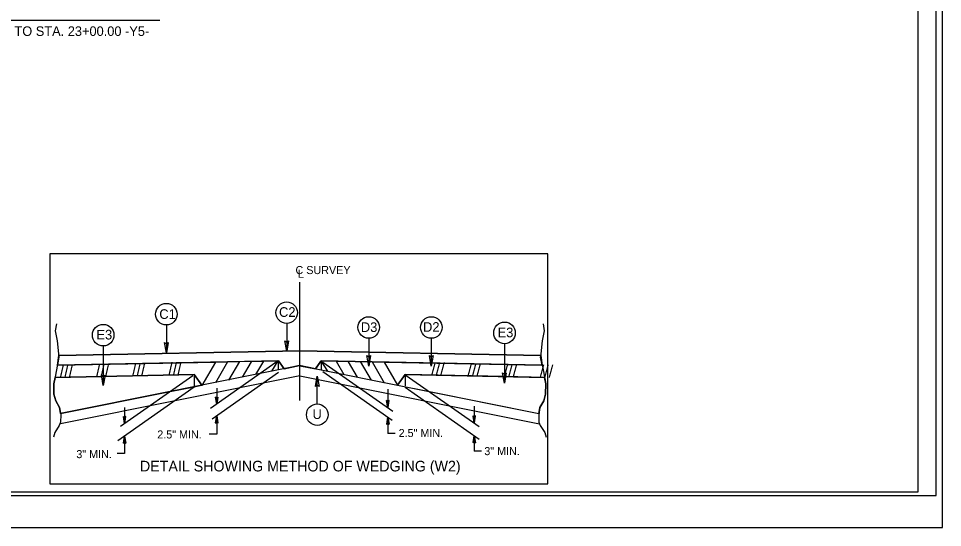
# Model space of a CAD drawing. Extents: x 2176156 to 2177167, y 76401 to 76644.
# Drawn here: x 2176795 to 2176898.7, y 76454.5 to 76511.6 of the extents above; entities that cross this region are included whole.
import ezdxf

# ---------------------------------------------------------------- set-up
doc = ezdxf.new("R2010")
doc.units = 0
for name, color, linetype in [('Exist Other Culture Fence Line', 7, 'Continuous'), ('Exist Utilities Water Fire Hydrant CELL', 7, 'Continuous'), ('Exist Vegetation Hedge Row', 7, 'Continuous'), ('Exist Vegetation Shrub CELL', 7, 'Continuous'), ('Exist Vegetation Woods Line', 7, 'Continuous'), ('Model Boundary Lines', 7, 'Continuous'), ('Model Boundary Lines Text', 7, 'Continuous'), ('Old_Level_1', 7, 'Continuous'), ('Prop North Arrow NAD83 for Plan Sheets CELL', 7, 'Continuous'), ('Scratch_Level_0', 7, 'Continuous'), ('Sheet Cutting Line CELL', 7, 'Continuous'), ('Sheet Data Field CELL', 7, 'Continuous'), ('Sheet Plot Border Outside CELL', 7, 'Continuous'), ('Sheet Sticker Exception Certification CELL', 7, 'Continuous')]:
    doc.layers.add(name, color=color, linetype=linetype)

msp = doc.modelspace()

# ---------------------------------------------------------------- linework, layer by layer
at = {"layer": 'Exist Other Culture Fence Line'}
msp.add_lwpolyline([(2176798.48, 76459.39), (2176854.4, 76459.39), (2176854.4, 76485.21), (2176798.48, 76485.21)], close=True, dxfattribs=at)
at = {"layer": 'Exist Utilities Water Fire Hydrant CELL'}
for p, q in [((2176799.33, 76472.69), (2176799.48, 76473.78)), ((2176826.54, 76474.32), (2176799.48, 76473.78)), ((2176799.48, 76473.78), (2176826.54, 76474.32)), ((2176826.54, 76474.32), (2176853.6, 76473.78)), ((2176826.54, 76474.32), (2176853.6, 76473.78)), ((2176853.6, 76473.78), (2176853.75, 76472.69)), ((2176824.17, 76473.19), (2176799.33, 76472.69)), ((2176824.17, 76473.19), (2176799.33, 76472.69)), ((2176826.58, 76472.65), (2176799.69, 76467.27)), ((2176817.07, 76473.04), (2176815.53, 76470.41)), ((2176824.13, 76473.17), (2176816.51, 76467.83)), ((2176818.42, 76473.07), (2176817.06, 76470.73)), ((2176819.76, 76473.1), (2176818.53, 76471)), ((2176821.1, 76473.09), (2176820.09, 76471.36)), ((2176822.46, 76473.16), (2176821.58, 76471.65)), ((2176823.4, 76472.03), (2176824.13, 76473.18)), ((2176824.13, 76473.18), (2176824.13, 76472.23)), ((2176824.77, 76472.29), (2176824.17, 76473.19)), ((2176824.17, 76473.16), (2176824.77, 76472.29)), ((2176826.5, 76472.65), (2176824.77, 76472.29)), ((2176826.5, 76472.65), (2176853.39, 76467.27)), ((2176828.3, 76472.29), (2176826.5, 76472.65)), ((2176828.93, 76473.19), (2176828.3, 76472.29)), ((2176828.93, 76473.19), (2176828.3, 76472.29)), ((2176828.89, 76473.17), (2176828.93, 76473.16)), ((2176828.93, 76473.19), (2176853.75, 76472.69)), ((2176853.75, 76472.69), (2176828.93, 76473.19)), ((2176829.68, 76472.03), (2176828.95, 76473.18)), ((2176828.95, 76473.18), (2176828.95, 76472.14)), ((2176829.14, 76473.04), (2176836.99, 76467.54)), ((2176830.62, 76473.16), (2176831.5, 76471.65)), ((2176831.98, 76473.09), (2176832.99, 76471.36)), ((2176833.32, 76473.1), (2176834.54, 76471)), ((2176834.66, 76473.07), (2176836.02, 76470.73)), ((2176836.01, 76473.04), (2176837.52, 76470.45)), ((2176814.7, 76471.64), (2176799.07, 76471.33)), ((2176799.07, 76471.33), (2176814.7, 76471.64)), ((2176814.52, 76471.51), (2176806.4, 76465.82)), ((2176815.55, 76470.44), (2176814.7, 76471.64)), ((2176814.7, 76471.64), (2176814.7, 76470.38)), ((2176814.7, 76471.64), (2176815.55, 76470.45)), ((2176824.15, 76471.86), (2176816.69, 76466.64)), ((2176829.13, 76471.97), (2176836.91, 76466.53)), ((2176838.37, 76471.64), (2176837.52, 76470.45)), ((2176837.53, 76470.45), (2176838.37, 76471.64)), ((2176838.37, 76471.64), (2176854.01, 76471.33)), ((2176838.37, 76471.64), (2176838.37, 76470.37)), ((2176849.53, 76471.42), (2176838.37, 76471.64)), ((2176838.5, 76471.55), (2176846.69, 76465.82)), ((2176826.53, 76471.5), (2176799.68, 76466.12)), ((2176826.55, 76471.5), (2176853.46, 76466.11)), ((2176854.01, 76471.33), (2176849.53, 76471.42)), ((2176811.98, 76469.73), (2176799.69, 76467.27)), ((2176814.7, 76470.23), (2176806.11, 76464.19)), ((2176814.7, 76470.28), (2176811.98, 76469.73)), ((2176815.55, 76470.45), (2176814.7, 76470.28)), ((2176817.21, 76470.13), (2176817.21, 76468.31)), ((2176836.42, 76470.02), (2176836.42, 76467.94)), ((2176837.52, 76470.45), (2176841.1, 76469.73)), ((2176838.37, 76470.21), (2176846.68, 76464.39)), ((2176841.1, 76469.73), (2176853.39, 76467.27)), ((2176817.21, 76468.31), (2176817.07, 76469.11)), ((2176817.21, 76469), (2176817.07, 76469.11)), ((2176817.21, 76468.31), (2176817.09, 76469.09)), ((2176817.11, 76469.08), (2176817.21, 76468.31)), ((2176817.21, 76468.31), (2176817.13, 76469.06)), ((2176817.15, 76469.05), (2176817.21, 76468.31)), ((2176817.21, 76468.31), (2176817.17, 76469.03)), ((2176817.19, 76469.02), (2176817.21, 76468.31)), ((2176817.21, 76468.31), (2176817.35, 76469.11)), ((2176817.35, 76469.11), (2176817.21, 76469)), ((2176817.33, 76469.09), (2176817.21, 76468.31)), ((2176817.21, 76468.31), (2176817.31, 76469.08)), ((2176817.29, 76469.06), (2176817.21, 76468.31)), ((2176817.21, 76468.31), (2176817.27, 76469.05)), ((2176817.25, 76469.03), (2176817.21, 76468.31)), ((2176817.21, 76468.31), (2176817.23, 76469.02)), ((2176817.21, 76469), (2176817.21, 76468.31)), ((2176836.42, 76467.94), (2176836.28, 76468.74)), ((2176836.42, 76468.64), (2176836.28, 76468.74)), ((2176836.42, 76467.94), (2176836.3, 76468.72)), ((2176836.32, 76468.71), (2176836.42, 76467.94)), ((2176836.42, 76467.94), (2176836.34, 76468.69)), ((2176836.36, 76468.68), (2176836.42, 76467.94)), ((2176836.42, 76467.94), (2176836.38, 76468.67)), ((2176836.4, 76468.65), (2176836.42, 76467.94)), ((2176836.42, 76467.94), (2176836.56, 76468.74)), ((2176836.56, 76468.74), (2176836.42, 76468.64)), ((2176836.54, 76468.72), (2176836.42, 76467.94)), ((2176836.42, 76467.94), (2176836.52, 76468.71)), ((2176836.5, 76468.69), (2176836.42, 76467.94)), ((2176836.42, 76467.94), (2176836.48, 76468.68)), ((2176836.46, 76468.67), (2176836.42, 76467.94)), ((2176836.42, 76467.94), (2176836.44, 76468.65)), ((2176836.42, 76468.64), (2176836.42, 76467.94)), ((2176806.87, 76467.96), (2176806.87, 76466.15)), ((2176846.13, 76468.09), (2176846.13, 76466.21)), ((2176806.87, 76466.15), (2176806.73, 76466.95)), ((2176806.87, 76466.84), (2176806.73, 76466.95)), ((2176806.87, 76466.15), (2176806.75, 76466.93)), ((2176806.77, 76466.92), (2176806.87, 76466.15)), ((2176806.87, 76466.15), (2176806.79, 76466.9)), ((2176806.81, 76466.89), (2176806.87, 76466.15)), ((2176806.87, 76466.15), (2176806.83, 76466.87)), ((2176806.85, 76466.86), (2176806.87, 76466.15)), ((2176806.87, 76466.15), (2176807.01, 76466.95)), ((2176807.01, 76466.95), (2176806.87, 76466.84)), ((2176806.99, 76466.93), (2176806.87, 76466.15)), ((2176806.87, 76466.15), (2176806.97, 76466.92)), ((2176806.95, 76466.9), (2176806.87, 76466.15)), ((2176806.87, 76466.15), (2176806.93, 76466.89)), ((2176806.91, 76466.87), (2176806.87, 76466.15)), ((2176806.87, 76466.15), (2176806.89, 76466.86)), ((2176806.87, 76466.84), (2176806.87, 76466.15)), ((2176817.21, 76467), (2176817.07, 76466.2)), ((2176817.09, 76466.22), (2176817.21, 76467)), ((2176817.21, 76467), (2176817.11, 76466.23)), ((2176817.13, 76466.25), (2176817.21, 76467)), ((2176817.21, 76467), (2176817.15, 76466.26)), ((2176817.17, 76466.27), (2176817.21, 76467)), ((2176817.21, 76467), (2176817.19, 76466.29)), ((2176817.21, 76467), (2176817.21, 76464.95)), ((2176817.21, 76467), (2176817.35, 76466.2)), ((2176817.21, 76466.3), (2176817.21, 76467)), ((2176817.23, 76466.29), (2176817.21, 76467)), ((2176817.21, 76467), (2176817.25, 76466.27)), ((2176817.27, 76466.26), (2176817.21, 76467)), ((2176817.21, 76467), (2176817.29, 76466.25)), ((2176817.31, 76466.23), (2176817.21, 76467)), ((2176817.21, 76467), (2176817.33, 76466.22)), ((2176836.42, 76466.87), (2176836.28, 76466.07)), ((2176836.3, 76466.09), (2176836.42, 76466.87)), ((2176836.42, 76466.87), (2176836.32, 76466.1)), ((2176836.34, 76466.12), (2176836.42, 76466.87)), ((2176836.42, 76466.87), (2176836.36, 76466.13)), ((2176836.38, 76466.15), (2176836.42, 76466.87)), ((2176836.42, 76466.87), (2176836.4, 76466.16)), ((2176836.42, 76466.87), (2176836.42, 76465.01)), ((2176836.42, 76466.87), (2176836.56, 76466.07)), ((2176836.42, 76466.17), (2176836.42, 76466.87)), ((2176836.44, 76466.16), (2176836.42, 76466.87)), ((2176836.42, 76466.87), (2176836.46, 76466.15)), ((2176836.48, 76466.13), (2176836.42, 76466.87)), ((2176836.42, 76466.87), (2176836.5, 76466.12)), ((2176836.52, 76466.1), (2176836.42, 76466.87)), ((2176836.42, 76466.87), (2176836.54, 76466.09)), ((2176846.13, 76466.21), (2176845.99, 76467.01)), ((2176846.13, 76466.9), (2176845.99, 76467.01)), ((2176846.13, 76466.21), (2176846.01, 76466.99)), ((2176846.03, 76466.98), (2176846.13, 76466.21)), ((2176846.13, 76466.21), (2176846.05, 76466.96)), ((2176846.07, 76466.95), (2176846.13, 76466.21)), ((2176846.13, 76466.21), (2176846.09, 76466.93)), ((2176846.11, 76466.92), (2176846.13, 76466.21)), ((2176846.13, 76466.21), (2176846.27, 76467.01)), ((2176846.27, 76467.01), (2176846.13, 76466.9)), ((2176846.25, 76466.99), (2176846.13, 76466.21)), ((2176846.13, 76466.21), (2176846.23, 76466.98)), ((2176846.21, 76466.96), (2176846.13, 76466.21)), ((2176846.13, 76466.21), (2176846.19, 76466.95)), ((2176846.17, 76466.93), (2176846.13, 76466.21)), ((2176846.13, 76466.21), (2176846.15, 76466.92)), ((2176846.13, 76466.9), (2176846.13, 76466.21)), ((2176817.07, 76466.2), (2176817.21, 76466.3)), ((2176817.21, 76466.3), (2176817.35, 76466.2)), ((2176836.28, 76466.07), (2176836.42, 76466.17)), ((2176836.42, 76466.17), (2176836.56, 76466.07)), ((2176806.87, 76464.72), (2176806.73, 76463.93)), ((2176806.75, 76463.94), (2176806.87, 76464.72)), ((2176806.87, 76464.72), (2176806.77, 76463.95)), ((2176806.79, 76463.97), (2176806.87, 76464.72)), ((2176806.87, 76464.72), (2176806.81, 76463.98)), ((2176806.83, 76464), (2176806.87, 76464.72)), ((2176806.87, 76464.72), (2176806.85, 76464.01)), ((2176806.87, 76464.72), (2176806.87, 76462.79)), ((2176806.87, 76464.72), (2176807.01, 76463.93)), ((2176806.87, 76464.03), (2176806.87, 76464.72)), ((2176806.89, 76464.01), (2176806.87, 76464.72)), ((2176806.87, 76464.72), (2176806.91, 76464)), ((2176806.93, 76463.98), (2176806.87, 76464.72)), ((2176806.87, 76464.72), (2176806.95, 76463.97)), ((2176806.97, 76463.95), (2176806.87, 76464.72)), ((2176806.87, 76464.72), (2176806.99, 76463.94)), ((2176817.21, 76464.95), (2176816.37, 76464.95)), ((2176837.25, 76465.01), (2176836.42, 76465.01)), ((2176846.13, 76464.78), (2176845.99, 76463.98)), ((2176846.01, 76464), (2176846.13, 76464.78)), ((2176846.13, 76464.78), (2176846.03, 76464.01)), ((2176846.05, 76464.03), (2176846.13, 76464.78)), ((2176846.13, 76464.78), (2176846.07, 76464.04)), ((2176846.09, 76464.06), (2176846.13, 76464.78)), ((2176846.13, 76464.78), (2176846.11, 76464.07)), ((2176846.13, 76464.78), (2176846.13, 76463.03)), ((2176846.13, 76464.78), (2176846.27, 76463.98)), ((2176846.13, 76464.09), (2176846.13, 76464.78)), ((2176846.15, 76464.07), (2176846.13, 76464.78)), ((2176846.13, 76464.78), (2176846.17, 76464.06)), ((2176846.19, 76464.04), (2176846.13, 76464.78)), ((2176846.13, 76464.78), (2176846.21, 76464.03)), ((2176846.23, 76464.01), (2176846.13, 76464.78)), ((2176846.13, 76464.78), (2176846.25, 76464)), ((2176806.73, 76463.93), (2176806.87, 76464.03)), ((2176806.87, 76464.03), (2176807.01, 76463.93)), ((2176845.99, 76463.98), (2176846.13, 76464.09)), ((2176846.13, 76464.09), (2176846.27, 76463.98)), ((2176806.87, 76462.79), (2176806.03, 76462.79)), ((2176846.96, 76463.03), (2176846.13, 76463.03))]:
    msp.add_line(p, q, dxfattribs=at)
for points in [[(2176799.23, 76477.35), (2176799.09, 76476.55), (2176799.3, 76475.43), (2176799.5, 76473.6), (2176799.23, 76472.16), (2176798.92, 76470.6), (2176798.94, 76469.43), (2176799.14, 76468.68), (2176799.57, 76467.94), (2176799.71, 76467.12), (2176799.69, 76466.31), (2176799.54, 76465.92), (2176799.04, 76465.15), (2176798.87, 76464.63)], [(2176853.85, 76477.35), (2176853.99, 76476.55), (2176853.77, 76475.43), (2176853.58, 76473.6), (2176853.85, 76472.16), (2176854.16, 76470.6), (2176854.13, 76469.43), (2176853.94, 76468.68), (2176853.51, 76467.94), (2176853.37, 76467.12), (2176853.39, 76466.31), (2176853.53, 76465.92), (2176854.04, 76465.15), (2176854.21, 76464.63)], [(2176799.69, 76467.27), (2176799.57, 76467.94), (2176799.14, 76468.68), (2176798.94, 76469.43), (2176798.92, 76470.6), (2176799.06, 76471.33)], [(2176853.39, 76467.27), (2176853.51, 76467.94), (2176853.94, 76468.68), (2176854.13, 76469.43), (2176854.16, 76470.6), (2176854.01, 76471.33)]]:
    msp.add_lwpolyline(points, dxfattribs=at)
at = {"layer": 'Exist Vegetation Shrub CELL'}
for p, q in [((2176811.56, 76477.21), (2176811.56, 76474.09)), ((2176825.07, 76477.38), (2176825.07, 76474.26)), ((2176834.28, 76475.72), (2176834.28, 76472.6)), ((2176841.31, 76475.72), (2176841.31, 76472.6)), ((2176804.48, 76474.86), (2176804.48, 76470.42)), ((2176849.53, 76475.11), (2176849.53, 76470.67)), ((2176828.5, 76468.35), (2176828.5, 76471.47))]:
    msp.add_line(p, q, dxfattribs=at)
for centre in [(2176811.56, 76478.42), (2176825.07, 76478.59), (2176834.28, 76476.93), (2176841.31, 76476.93), (2176804.47, 76476.07), (2176849.53, 76476.32), (2176828.5, 76467.14)]:
    msp.add_circle(centre, 1.21, dxfattribs=at)
at = {"layer": 'Model Boundary Lines Text'}
msp.add_line((2176783.49, 76511.42), (2176810.81, 76511.42), dxfattribs=at)
at = {"layer": 'Old_Level_1'}
for points in [[(2176811.76, 76475.26), (2176811.56, 76474.09), (2176811.35, 76475.26), (2176811.56, 76475.11)], [(2176811.76, 76475.26), (2176811.56, 76474.09), (2176811.35, 76475.26), (2176811.56, 76475.11)], [(2176825.27, 76475.43), (2176825.07, 76474.26), (2176824.86, 76475.44), (2176825.07, 76475.29)], [(2176825.27, 76475.43), (2176825.07, 76474.26), (2176824.86, 76475.44), (2176825.07, 76475.29)], [(2176834.48, 76473.77), (2176834.28, 76472.6), (2176834.07, 76473.78), (2176834.28, 76473.63)], [(2176834.48, 76473.77), (2176834.28, 76472.6), (2176834.07, 76473.78), (2176834.28, 76473.63)], [(2176841.51, 76473.77), (2176841.31, 76472.6), (2176841.1, 76473.78), (2176841.31, 76473.63)], [(2176841.51, 76473.77), (2176841.31, 76472.6), (2176841.1, 76473.78), (2176841.31, 76473.63)], [(2176804.68, 76471.59), (2176804.48, 76470.42), (2176804.27, 76471.6), (2176804.48, 76471.45)], [(2176804.68, 76471.59), (2176804.48, 76470.42), (2176804.27, 76471.6), (2176804.48, 76471.45)], [(2176849.73, 76471.84), (2176849.53, 76470.67), (2176849.32, 76471.85), (2176849.53, 76471.7)], [(2176828.3, 76470.3), (2176828.5, 76471.47), (2176828.71, 76470.29), (2176828.5, 76470.44)], [(2176828.3, 76470.3), (2176828.5, 76471.47), (2176828.71, 76470.29), (2176828.5, 76470.44)]]:
    msp.add_lwpolyline(points, close=True, dxfattribs=at)
at = {"layer": 'Prop North Arrow NAD83 for Plan Sheets CELL'}
for p, q in [((2176826.54, 76468.75), (2176826.54, 76482.01)), ((2176826.54, 76474.32), (2176799.48, 76473.78)), ((2176799.48, 76473.78), (2176799.48, 76473.75)), ((2176853.6, 76473.75), (2176853.6, 76473.78)), ((2176799.33, 76472.69), (2176817.07, 76473.04)), ((2176799.33, 76472.72), (2176799.33, 76472.69)), ((2176817.07, 76473.04), (2176818.42, 76473.07)), ((2176818.42, 76473.07), (2176818.42, 76473.07)), ((2176824.17, 76473.19), (2176824.77, 76472.29)), ((2176824.77, 76472.29), (2176826.5, 76472.65)), ((2176828.93, 76473.19), (2176830.62, 76473.15)), ((2176834.66, 76473.07), (2176834.66, 76473.07)), ((2176834.66, 76473.07), (2176836.01, 76473.04)), ((2176836.01, 76473.04), (2176853.75, 76472.69)), ((2176814.7, 76471.64), (2176799.07, 76471.33)), ((2176815.55, 76470.45), (2176814.7, 76471.64)), ((2176838.37, 76471.64), (2176837.52, 76470.45)), ((2176849.53, 76471.42), (2176838.37, 76471.64)), ((2176799.07, 76471.33), (2176798.92, 76470.6)), ((2176854.01, 76471.33), (2176849.53, 76471.42)), ((2176841.1, 76469.73), (2176853.39, 76467.27)), ((2176853.51, 76467.94), (2176853.94, 76468.68)), ((2176799.57, 76467.94), (2176799.69, 76467.27)), ((2176853.39, 76467.27), (2176853.51, 76467.94))]:
    msp.add_line(p, q, dxfattribs=at)
for points in [[(2176799.48, 76473.75), (2176799.5, 76473.6), (2176799.33, 76472.72)], [(2176853.6, 76473.78), (2176826.54, 76474.32), (2176826.54, 76474.32)], [(2176853.75, 76472.69), (2176853.58, 76473.6), (2176853.6, 76473.75)], [(2176818.42, 76473.07), (2176819.76, 76473.1), (2176822.45, 76473.15), (2176824.17, 76473.19)], [(2176818.42, 76473.07), (2176818.42, 76473.07)], [(2176826.5, 76472.65), (2176826.54, 76472.64), (2176828.3, 76472.29)], [(2176828.3, 76472.29), (2176828.92, 76473.16), (2176828.93, 76473.19)], [(2176830.62, 76473.15), (2176833.32, 76473.1), (2176834.66, 76473.07)], [(2176834.66, 76473.07), (2176834.66, 76473.07)], [(2176798.92, 76470.6), (2176798.94, 76469.43), (2176799.14, 76468.68), (2176799.57, 76467.94)], [(2176853.94, 76468.68), (2176854.13, 76469.43), (2176854.16, 76470.6), (2176854.01, 76471.33)], [(2176799.69, 76467.27), (2176811.98, 76469.73), (2176811.98, 76469.73), (2176814.7, 76470.28)], [(2176814.7, 76470.28), (2176815.51, 76470.44), (2176815.55, 76470.45)], [(2176837.52, 76470.45), (2176841.1, 76469.73), (2176841.1, 76469.73)]]:
    msp.add_lwpolyline(points, dxfattribs=at)
at = {"layer": 'Sheet Cutting Line CELL'}
msp.add_lwpolyline([(2176898.71, 76630.48), (2176629.27, 76630.48), (2176629.27, 76454.48), (2176898.71, 76454.48)], close=True, dxfattribs=at)
at = {"layer": 'Sheet Data Field CELL'}
msp.add_lwpolyline([(2176895.99, 76626.48), (2176655.99, 76626.48), (2176655.99, 76458.48), (2176895.99, 76458.48)], close=True, dxfattribs=at)
at = {"layer": 'Sheet Plot Border Outside CELL'}
msp.add_lwpolyline([(2176897.99, 76626.88), (2176631.35, 76626.88), (2176631.35, 76458.07), (2176897.99, 76458.07)], close=True, dxfattribs=at)
at = {"layer": 'Sheet Sticker Exception Certification CELL'}
msp.add_line((2176629.27, 76454.48), (2176898.71, 76454.48), dxfattribs=at)

# ---------------------------------------------------------------- texts
at = {"layer": 'Exist Utilities Water Fire Hydrant CELL'}
for height, rotation, p in [(1.357, 1.1447, (2176799.6, 76471.35)), (1.357, 1.1464, (2176803.66, 76471.39)), (1.356, 1.1445, (2176807.72, 76471.51)), (1.356, 1.1463, (2176811.79, 76471.6)), (1.356, 358.8553, (2176841.29, 76471.6)), (1.356, 358.8536, (2176845.36, 76471.51)), (1.357, 358.8554, (2176849.42, 76471.39)), (1.357, 358.8537, (2176853.47, 76471.35))]:
    msp.add_text('/// ', height=height, rotation=rotation, dxfattribs=at).set_placement(p)
for s, p in [('2.5" MIN.', (2176810.54, 76464.47)), ('2.5" MIN.', (2176837.64, 76464.63)), ('3" MIN.', (2176847.26, 76462.6)), ('3" MIN.', (2176801.45, 76462.26))]:
    msp.add_text(s, height=0.904, dxfattribs=at).set_placement(p)
at = {"layer": 'Exist Vegetation Hedge Row'}
for s, height, p in [('C1', 1.082, (2176810.77, 76477.89)), ('C2', 1.082, (2176824.21, 76478.12)), ('D3', 1.082, (2176833.4, 76476.42)), ('D2', 1.082, (2176840.38, 76476.44)), ('E3', 1.082, (2176848.75, 76475.83)), ('E3', 1.082, (2176803.71, 76475.58)), ('U', 1.08, (2176827.97, 76466.66))]:
    msp.add_text(s, height=height, dxfattribs=at).set_placement(p)
at = {"layer": 'Exist Vegetation Woods Line'}
msp.add_text('STA. 12+06.83 -Y5- TO STA. 23+00.00 -Y5-', height=1.0742, dxfattribs=at).set_placement((2176781.37, 76509.65))
at = {"layer": 'Model Boundary Lines'}
msp.add_text('DETAIL SHOWING METHOD OF WEDGING (W2)', height=1.1936, dxfattribs=at).set_placement((2176808.6, 76460.77))
at = {"layer": 'Scratch_Level_0'}
for s, p in [('C SURVEY ', (2176826.06, 76482.92)), ('L', (2176826.33, 76482.5))]:
    msp.add_text(s, height=0.904, dxfattribs=at).set_placement(p)

doc.saveas('drawing.dxf')
